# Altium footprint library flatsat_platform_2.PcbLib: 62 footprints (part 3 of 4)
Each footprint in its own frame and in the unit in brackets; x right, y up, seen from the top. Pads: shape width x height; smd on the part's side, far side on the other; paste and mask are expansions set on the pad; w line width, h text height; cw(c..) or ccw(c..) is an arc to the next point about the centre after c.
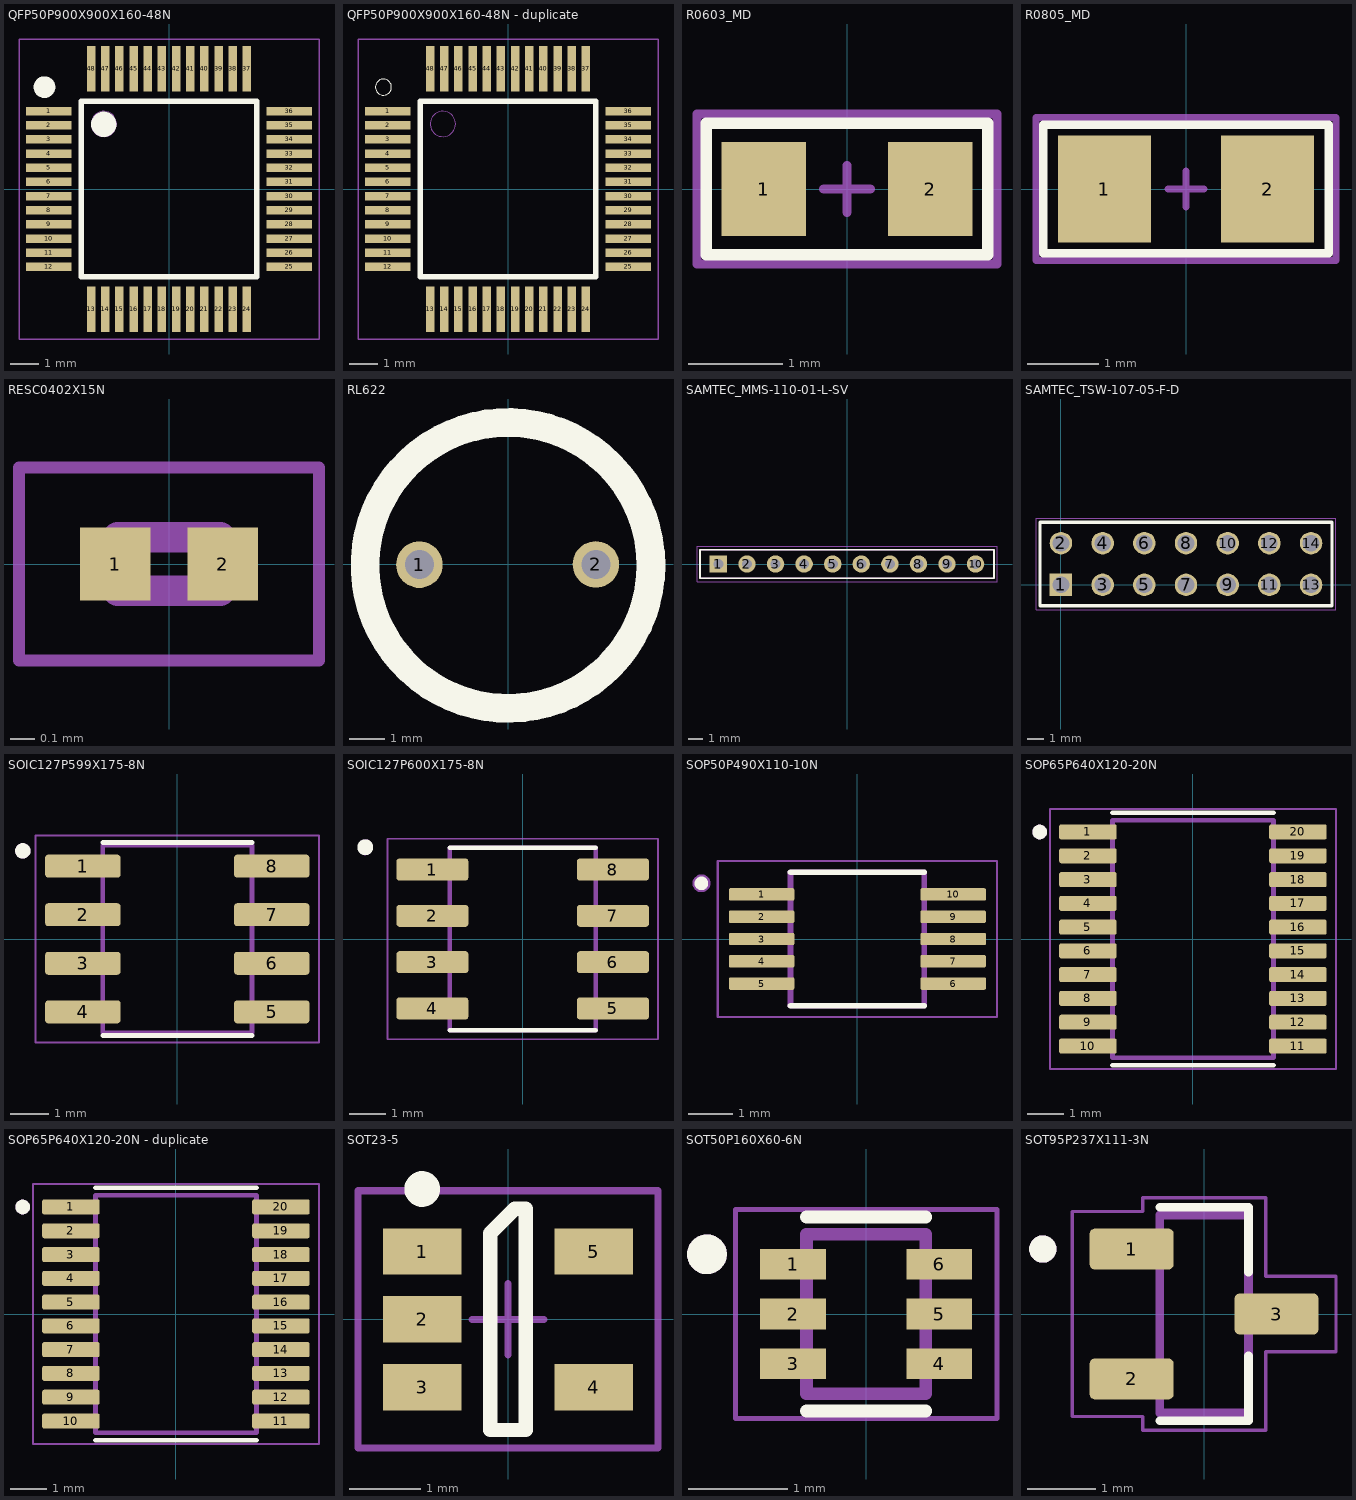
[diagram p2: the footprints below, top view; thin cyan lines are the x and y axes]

## QFP50P900X900X160-48N [mm]
pads (48):
  rect 1.6x0.3 smd: 1(-4.25,2.75) 2(-4.25,2.25) 3(-4.25,1.75) 4(-4.25,1.25) 5(-4.25,0.75) 6(-4.25,0.25) 7(-4.25,-0.25) 8(-4.25,-0.75) 9(-4.25,-1.25) 10(-4.25,-1.75) 11(-4.25,-2.25) 12(-4.25,-2.75) 25(4.25,-2.75) 26(4.25,-2.25) 27(4.25,-1.75) 28(4.25,-1.25) 29(4.25,-0.75) 30(4.25,-0.25) 31(4.25,0.25) 32(4.25,0.75) 33(4.25,1.25) 34(4.25,1.75) 35(4.25,2.25) 36(4.25,2.75)
  rect 0.3x1.6 smd: 13(-2.75,-4.25) 14(-2.25,-4.25) 15(-1.75,-4.25) 16(-1.25,-4.25) 17(-0.75,-4.25) 18(-0.25,-4.25) 19(0.25,-4.25) 20(0.75,-4.25) 21(1.25,-4.25) 22(1.75,-4.25) 23(2.25,-4.25) 24(2.75,-4.25) 37(2.75,4.25) 38(2.25,4.25) 39(1.75,4.25) 40(1.25,4.25) 41(0.75,4.25) 42(0.25,4.25) 43(-0.25,4.25) 44(-0.75,4.25) 45(-1.25,4.25) 46(-1.75,4.25) 47(-2.25,4.25) 48(-2.75,4.25)
Top Overlay:
  circle w0.508: c-4.4,3.6 r0.127
  lines w0.2: -3.1,-3.1 3.1,-3.1 3.1,3.1 -3.1,3.1 -3.1,-3.1
  lines w0.635: -2.186,2.331 ccw(c-2.305,2.286) -2.178,2.286
Mechanical 13:
  circle w0: c-2.3,2.3 r0.447
Mechanical 15:
  lines w0.05: -5.3,-5.3 5.3,-5.3 5.3,5.3 -5.3,5.3 -5.3,-5.3
3D body "LQFP-48_LX_LIT-L.step": height 1.6, standoff 0, extent -4.5,-4.5 4.5,4.5

## QFP50P900X900X160-48N - duplicate [mm]
pads (48):
  rect 1.6x0.3 smd: 1(-4.25,2.75) 2(-4.25,2.25) 3(-4.25,1.75) 4(-4.25,1.25) 5(-4.25,0.75) 6(-4.25,0.25) 7(-4.25,-0.25) 8(-4.25,-0.75) 9(-4.25,-1.25) 10(-4.25,-1.75) 11(-4.25,-2.25) 12(-4.25,-2.75) 25(4.25,-2.75) 26(4.25,-2.25) 27(4.25,-1.75) 28(4.25,-1.25) 29(4.25,-0.75) 30(4.25,-0.25) 31(4.25,0.25) 32(4.25,0.75) 33(4.25,1.25) 34(4.25,1.75) 35(4.25,2.25) 36(4.25,2.75)
  rect 0.3x1.6 smd: 13(-2.75,-4.25) 14(-2.25,-4.25) 15(-1.75,-4.25) 16(-1.25,-4.25) 17(-0.75,-4.25) 18(-0.25,-4.25) 19(0.25,-4.25) 20(0.75,-4.25) 21(1.25,-4.25) 22(1.75,-4.25) 23(2.25,-4.25) 24(2.75,-4.25) 37(2.75,4.25) 38(2.25,4.25) 39(1.75,4.25) 40(1.25,4.25) 41(0.75,4.25) 42(0.25,4.25) 43(-0.25,4.25) 44(-0.75,4.25) 45(-1.25,4.25) 46(-1.75,4.25) 47(-2.25,4.25) 48(-2.75,4.25)
Top Overlay:
  circle w0: c-4.4,3.6 r0.283
  lines w0.2: -3.1,-3.1 -3.1,3.1 3.1,3.1 3.1,-3.1 -3.1,-3.1
Mechanical 13:
  circle w0: c-2.3,2.3 r0.447
Mechanical 15:
  lines w0.05: -5.3,-5.3 -5.3,5.3 5.3,5.3 5.3,-5.3 -5.3,-5.3
3D body "MSP430FR2355TPT.STEP": height 1.6, standoff 0, extent -4.5,-4.5 4.5,4.5

## R0603_MD [mm] "Chip Resistor, Body 1.6x0.8mm, IPC Medium Density"
height 0.85
pads (2):
  rect 0.9x1 smd: 1(-0.889,0) 2(0.889,0)
Top Overlay:
  lines w0.12: -1.5,-0.7 -1.5,0.7 1.5,0.7 1.5,-0.7 -1.5,-0.7
Top Assembly:
  lines w0.1: -0.25,0 0.25,0 ; 0,-0.25 0,0.25 ; -1.6,-0.8 -1.6,0.8 1.6,0.8 1.6,-0.8 -1.6,-0.8
  text "'.Designator'" at -1.4,-0.6 h0.8
3D body "Flat Chip Resistor 0603(1608M).step": height 0.37, standoff 0, extent -0.8,-0.4 0.8,0.402

## R0805_MD [mm] "Chip Resistor, Body 2.0x1.3mm, IPC Medium Density"
height 1.1
pads (2):
  rect 1.3x1.5 smd: 1(-1.143,0) 2(1.143,0)
Top Overlay:
  lines w0.12: -2,-0.9 2,-0.9 2,0.9 -2,0.9 -2,-0.9
Top Assembly:
  lines w0.1: -0.25,0 0.25,0 ; 0,-0.25 0,0.25 ; -2.1,-1 -2.1,1 2.1,1 2.1,-1 -2.1,-1
  text "'.Designator'" at -1.75,-0.75 h0.8
3D body "Flat Chip Resistor 0805(2012M).step": height 0.47, standoff 0, extent -1,-0.625 1,0.627

## RESC0402X15N [mm]
pads (2):
  rect 0.29x0.3 smd: 1(-0.222,0) 2(0.222,0)
Mechanical 13:
  lines w0.127: -0.21,-0.11 -0.21,0.11 0.21,0.11 0.21,-0.11 -0.21,-0.11
Mechanical 15:
  lines w0.05: -0.619,-0.399 -0.619,0.399 0.619,0.399 0.619,-0.399 -0.619,-0.399
3D body "ERJ-XGNF1203Y.STEP": height 0.16, standoff 0.01, extent -0.2,-0.1 0.2,0.1

## RL622 [mm]
pads (2):
  round 1.32 hole 0.82: 1(-2.51,-0.02) 2(2.49,-0.01)
Top Overlay:
  circle w0.813: c0,-0.04 r4.05
Mechanical 13:
  circle w0.2: c0,0 r4.25
3D body "rl622-3r3k-rc.stp": height 11.01, standoff -4.99, extent -4.25,-4.25 4.25,4.25

## SAMTEC_MMS-110-01-L-SV [mm]
pads (10):
  rect 1.219x1.219 hole 0.711: 1(-9,0)
  round 1.219 hole 0.711: 2(-7,0) 3(-5,0) 4(-3,0) 5(-1,0) 6(1,0) 7(3,0) 8(5,0) 9(7,0) 10(9,0)
Top Overlay:
  lines w0.127: -10.28,-1 10.28,-1 10.28,1 -10.28,1 -10.28,-1
Mechanical 13:
  circle w0.2: c-9,0 r0.1
  lines w0.127: -10.28,-1 -10.28,1 10.28,1 10.28,-1 -10.28,-1
Mechanical 15:
  lines w0.05: -10.5,-1.25 10.5,-1.25 10.5,1.25 -10.5,1.25 -10.5,-1.25
3D body "MMS-110-01-L-SV-01.stp": height 4.46, standoff -2.91, extent -10.274,-1 10.274,1

## SAMTEC_TSW-107-05-F-D [mm]
pads (14):
  rect 1.37x1.37 hole 1.02: 1(0,0)
  round 1.37 hole 1.02: 2(0,2.54) 3(2.54,0) 4(2.54,2.54) 5(5.08,0) 6(5.08,2.54) 7(7.62,0) 8(7.62,2.54) 9(10.16,0) 10(10.16,2.54) 11(12.7,0) 12(12.7,2.54) 13(15.24,0) 14(15.24,2.54)
Top Overlay:
  lines w0.2: -1.27,-1.27 -1.27,3.81 16.51,3.81 16.51,-1.27 -1.27,-1.27
Mechanical 13:
  lines w0.1: -1.27,-1.27 -1.27,3.81 16.51,3.81 16.51,-1.27 -1.27,-1.27
Mechanical 15:
  lines w0.05: -1.52,-1.52 -1.52,4.06 16.76,4.06 16.76,-1.52 -1.52,-1.52
3D body "TSW-107-05-F-D.stp": height 5.22, standoff -3.29, extent -1.27,-1.27 16.51,3.81

## SOIC127P599X175-8N [mm]
pads (8):
  rrect25% 1.97x0.6 smd: 1(-2.47,1.905) 2(-2.47,0.635) 3(-2.47,-0.635) 4(-2.47,-1.905) 5(2.47,-1.905) 6(2.47,-0.635) 7(2.47,0.635) 8(2.47,1.905)
Top Overlay:
  circle w0.2: c-4.04,2.305 r0.1
  lines w0.127: -1.95,-2.525 1.95,-2.525 ; -1.95,2.525 1.95,2.525
Mechanical 13:
  circle w0.2: c-4.04,2.305 r0.1
  lines w0.127: -1.95,-2.452 1.95,-2.452 1.95,2.452 -1.95,2.452 -1.95,-2.452
Mechanical 15:
  lines w0.05: -3.705,-2.702 3.705,-2.702 3.705,2.702 -3.705,2.702 -3.705,-2.702
3D body "SN65HVD232D.STEP": height 1.75, standoff 0, extent -2.997,-2.451 2.998,2.451

## SOIC127P600X175-8N [mm]
pads (8):
  rrect25% 1.97x0.6 smd: 1(-2.475,1.905) 2(-2.475,0.635) 3(-2.475,-0.635) 4(-2.475,-1.905) 5(2.475,-1.905) 6(2.475,-0.635) 7(2.475,0.635) 8(2.475,1.905)
Top Overlay:
  circle w0.381: c-4.315,2.515 r0.025
  lines w0.127: -2,-2.5 2,-2.5 ; -2,2.5 2,2.5
Mechanical 13:
  circle w0: c-4.315,2.515 r0.2
  lines w0.127: -2,-2.5 2,-2.5 2,2.5 -2,2.5 -2,-2.5
Mechanical 15:
  lines w0.05: -3.71,-2.75 3.71,-2.75 3.71,2.75 -3.71,2.75 -3.71,-2.75
3D body "IC_Renesas_ISL83485IBZ-T_eec.STEP": height 1.75, standoff 0, extent -3,-2.45 3,2.45

## SOP50P490X110-10N [mm]
pads (10):
  rrect25% 1.47x0.28 smd: 1(-2.15,1) 2(-2.15,0.5) 3(-2.15,0) 4(-2.15,-0.5) 5(-2.15,-1) 6(2.15,-1) 7(2.15,-0.5) 8(2.15,0) 9(2.15,0.5) 10(2.15,1)
Top Overlay:
  circle w0.254: c-3.5,1.25 r0.025
  lines w0.127: -1.5,-1.5 1.5,-1.5 ; -1.5,1.5 1.5,1.5
Mechanical 13:
  circle w0.2: c-3.5,1.25 r0.1
  lines w0.127: -1.5,-1.5 1.5,-1.5 1.5,1.5 -1.5,1.5 -1.5,-1.5
Mechanical 15:
  lines w0.05: -3.135,-1.75 3.135,-1.75 3.135,1.75 -3.135,1.75 -3.135,-1.75
3D body "step_temp.STEP": height 1.1, standoff 0, extent -2.45,-1.5 2.45,1.5

## SOP65P640X120-20N [mm]
pads (20):
  rrect25% 1.57x0.41 smd: 1(-2.87,2.925) 2(-2.87,2.275) 3(-2.87,1.625) 4(-2.87,0.975) 5(-2.87,0.325) 6(-2.87,-0.325) 7(-2.87,-0.975) 8(-2.87,-1.625) 9(-2.87,-2.275) 10(-2.87,-2.925) 11(2.87,-2.925) 12(2.87,-2.275) 13(2.87,-1.625) 14(2.87,-0.975) 15(2.87,-0.325) 16(2.87,0.325) 17(2.87,0.975) 18(2.87,1.625) 19(2.87,2.275) 20(2.87,2.925)
Top Overlay:
  circle w0.2: c-4.19,2.925 r0.1
  lines w0.127: -2.2,-3.45 2.2,-3.45 ; -2.2,3.45 2.2,3.45
Mechanical 13:
  circle w0.2: c-4.19,2.925 r0.1
  lines w0.127: -2.2,-3.25 2.2,-3.25 2.2,3.25 -2.2,3.25 -2.2,-3.25
Mechanical 15:
  lines w0.05: -3.91,-3.55 3.91,-3.55 3.91,3.55 -3.91,3.55 -3.91,-3.55
3D body "TXB0108PWR.STEP": height 1.2, standoff 0, extent -3.2,-3.25 3.2,3.25

## SOP65P640X120-20N - duplicate [mm]
pads (20):
  rrect25% 1.57x0.41 smd: 1(-2.87,2.925) 2(-2.87,2.275) 3(-2.87,1.625) 4(-2.87,0.975) 5(-2.87,0.325) 6(-2.87,-0.325) 7(-2.87,-0.975) 8(-2.87,-1.625) 9(-2.87,-2.275) 10(-2.87,-2.925) 11(2.87,-2.925) 12(2.87,-2.275) 13(2.87,-1.625) 14(2.87,-0.975) 15(2.87,-0.325) 16(2.87,0.325) 17(2.87,0.975) 18(2.87,1.625) 19(2.87,2.275) 20(2.87,2.925)
Top Overlay:
  circle w0.2: c-4.19,2.925 r0.1
  lines w0.127: -2.2,-3.45 2.2,-3.45 ; -2.2,3.45 2.2,3.45
Mechanical 13:
  circle w0.2: c-4.19,2.925 r0.1
  lines w0.127: -2.2,-3.25 2.2,-3.25 2.2,3.25 -2.2,3.25 -2.2,-3.25
Mechanical 15:
  lines w0.05: -3.91,-3.55 -3.91,3.55 3.91,3.55 3.91,-3.55 -3.91,-3.55
3D body "TXS0108EPWR.STEP": height 1.2, standoff 0, extent -3.2,-3.25 3.2,3.25

## SOT23-5 [mm]
height 1.45
pads (5):
  rect 1.1x0.65 smd: 1(-1.2,0.95) 2(-1.2,0) 3(-1.2,-0.95) 4(1.2,-0.95) 5(1.2,0.95)
Top Overlay:
  circle w0.25: c-1.2,1.825 r0.125
  lines w0.2: -0.25,-1.55 -0.25,1.206 0.094,1.55 0.25,1.55 0.25,-1.55 -0.25,-1.55
Top Assembly:
  lines w0.1: -0.5,0 0.5,0 ; 0,-0.5 0,0.5 ; -2.1,-1.8 2.1,-1.8 2.1,1.8 -2.1,1.8 -2.1,-1.8
  text "'.Designator'" at -1.75,0.75 h0.8
3D body "SOT23-5.STEP": height 1.3, standoff 0, extent -1.5,-1.5 1.5,1.5

## SOT50P160X60-6N [mm]
pads (6):
  rect 0.66x0.31 smd: 1(-0.735,0.5) 2(-0.735,0) 3(-0.735,-0.5) 4(0.735,-0.5) 5(0.735,0) 6(0.735,0.5)
Top Overlay:
  circle w0.2: c-1.6,0.6 r0.1
  lines w0.127: -0.6,-0.975 0.6,-0.975 ; -0.6,0.975 0.6,0.975
Mechanical 13:
  circle w0.2: c-1.6,0.6 r0.1
  lines w0.127: -0.6,-0.8 -0.6,0.8 0.6,0.8 0.6,-0.8 -0.6,-0.8
Mechanical 15:
  lines w0.05: -1.315,-1.05 -1.315,1.05 1.315,1.05 1.315,-1.05 -1.315,-1.05
3D body "TMP112AIDRLT.STEP": height 0.61, standoff 0.01, extent -0.8,-0.8 0.8,0.8

## SOT95P237X111-3N [mm]
pads (3):
  rrect25% 1.23x0.6 smd: 1(-1.06,0.95) 2(-1.06,-0.95) 3(1.06,0)
Top Overlay:
  circle w0.2: c-2.36,0.95 r0.1
  lines w0.127: -0.65,-1.564 0.65,-1.564 0.65,-0.614 ; -0.65,1.564 0.65,1.564 0.65,0.614
Mechanical 13:
  circle w0.2: c-2.36,0.95 r0.1
  lines w0.127: -0.65,-1.45 0.65,-1.45 0.65,1.45 -0.65,1.45 -0.65,-1.45
Mechanical 15:
  lines w0.05: -1.93,-1.5 -1.93,1.5 -0.9,1.5 -0.9,1.7 0.9,1.7 0.9,0.55 1.93,0.55 1.93,-0.55 0.9,-0.55 0.9,-1.7 -0.9,-1.7 -0.9,-1.5 -1.93,-1.5
3D body "step_temp.STEP": height 1.11, standoff 0, extent -1.2,-1.45 1.2,1.45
